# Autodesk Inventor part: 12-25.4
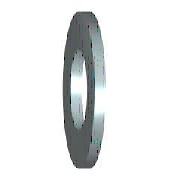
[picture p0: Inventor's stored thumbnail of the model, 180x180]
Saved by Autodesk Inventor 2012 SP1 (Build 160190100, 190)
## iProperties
Created: 2006-02
Material: Steel, Mild
Description: Plain Washer
Document SubType Name: Modeling
Standard: ANSI B18.22 M
Designer: Administrator
Standards Organization: ANSI
Language: en-US
Categories: <MemberInstance><Categories><Category DisplayName="Fasteners" InternalName="e4da775c-781d-43d5-af7c-5136215cf5a6" Mnemonic="FSTN"><Category DisplayName="Washers
Density: 1 g/cm^3
Author: Administrator
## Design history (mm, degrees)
workaxis "Work Axis1"
workplane "Work Plane1"
body "Solid1"
sketch "Sketch"
  geometry: C1 r 12.7 at (0, 0); C2 r 6.65 at (0, 0); 1 further point
  constraints: 2 centre point, 2 coincident
  dimensions: "d0" = 13.3 diameter of C2 (= SD1); "d1" = 25.4 diameter of C1 (= SD2)
extrude "Body" new body sketch "Sketch" distance "d2" = 2.8 (= SD); taper "d3" = 0 deg
other parameters: "SD1" = 13.3 [user parameter; used in 1 equation term], "SD2" = 25.4 [user parameter; used in 1 equation term], "SD" = 2.8 [user parameter; used in 1 equation term], "d4" = 0, "d5" = 0, "d6" = 0, "d7" = 0, "NND" = 12 [user parameter]
